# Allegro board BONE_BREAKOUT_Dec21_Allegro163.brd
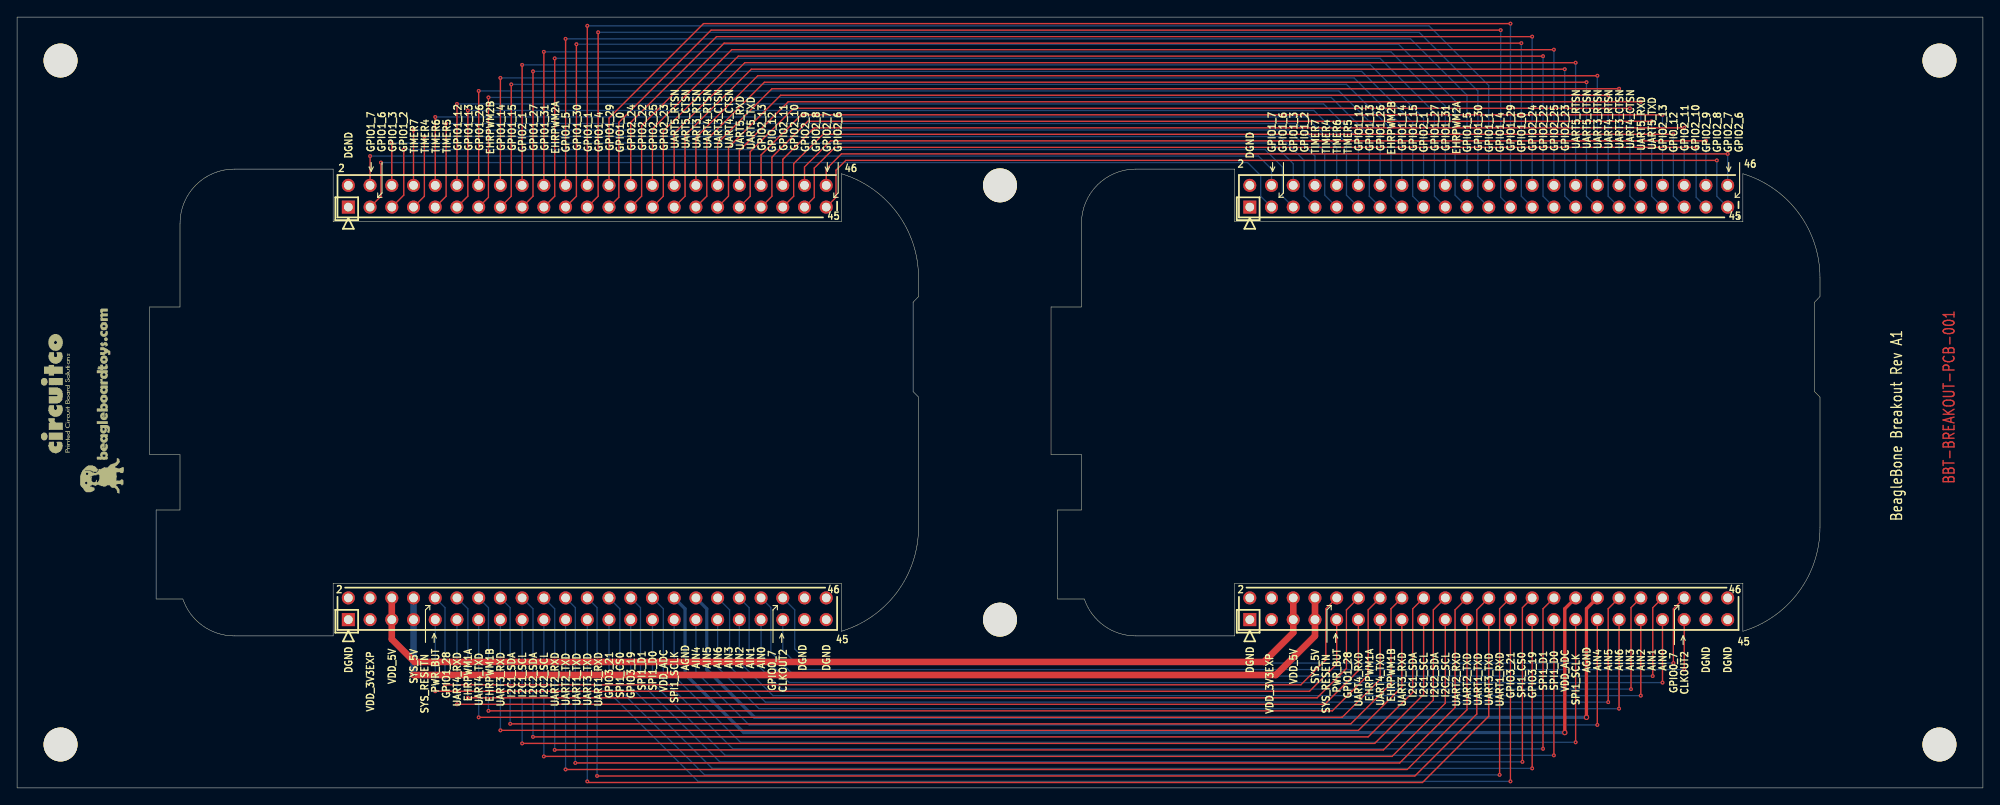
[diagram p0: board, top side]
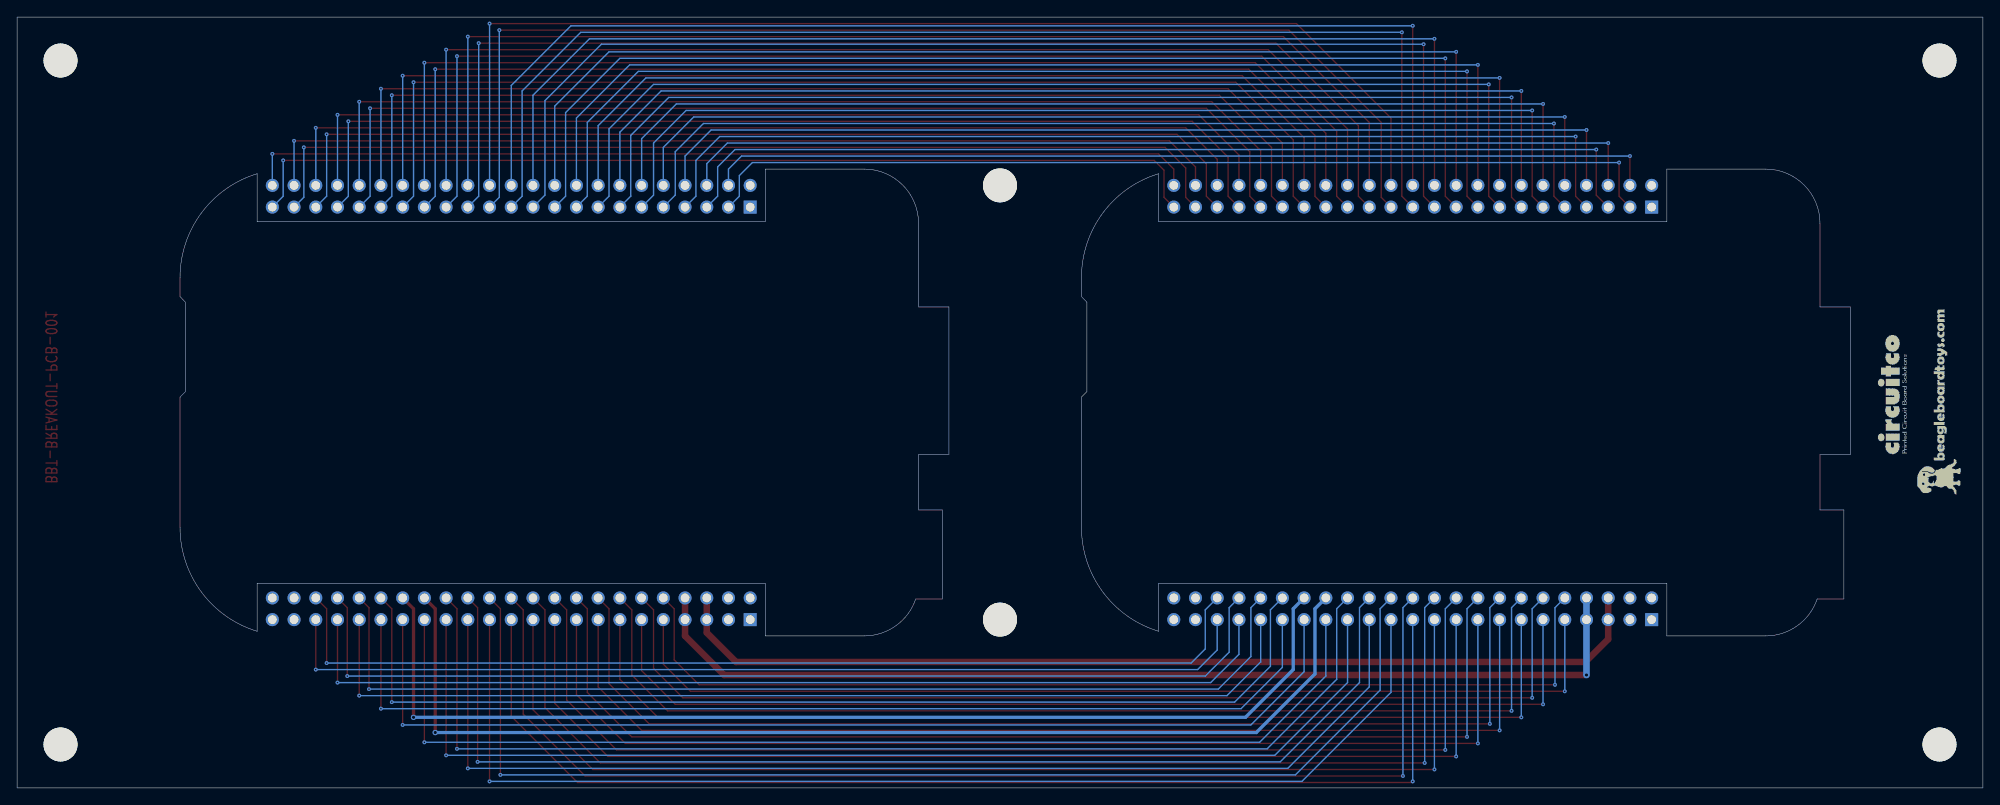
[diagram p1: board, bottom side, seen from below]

Outline 229.87 x 90.17 mm; copper layers: TOP, LYR2-GND, LYR3-PWR, BOTTOM. Coordinates in mm from the lower left corner of the outline.

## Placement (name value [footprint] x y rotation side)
NOREF  -  []  -339.09 -213.36 0 top
NOREF#2  -  [unnamed#2]  19.05 17.78 0 top
P1  FEMALE HEADER 2x23  [2X23_HDR_FEMALE]  38.73 67.94 180 top
P2  FEMALE HEADER 2x23  [2X23_HDR_FEMALE]  38.73 19.69 180 top
P3  FEMALE HEADER 2x23  [2X23_HDR_FEMALE]  144.15 67.94 180 top
P4  FEMALE HEADER 2x23  [2X23_HDR_FEMALE]  144.15 19.69 180 top

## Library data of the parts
P1-P4 = FEMALE HEADER 2x23

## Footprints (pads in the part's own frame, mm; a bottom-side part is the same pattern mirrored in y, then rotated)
2X23_HDR_FEMALE
  rect 1.524x1.524 hole 1.016: 1(0,0)
  round 1.524 hole 1.016: 2(0,-2.54) 3(-2.54,0) 4(-2.54,-2.54) 5(-5.08,0) 6(-5.08,-2.54) 7(-7.62,0) 8(-7.62,-2.54) 9(-10.16,0) 10(-10.16,-2.54) 11(-12.7,0) 12(-12.7,-2.54) 13(-15.24,0) 14(-15.24,-2.54) 15(-17.78,0) 16(-17.78,-2.54) 17(-20.32,0) 18(-20.32,-2.54) 19(-22.86,0) 20(-22.86,-2.54) 21(-25.4,0) 22(-25.4,-2.54) 23(-27.94,0) 24(-27.94,-2.54) 25(-30.48,0) 26(-30.48,-2.54) 27(-33.02,0) 28(-33.02,-2.54) 29(-35.56,0) 30(-35.56,-2.54) 31(-38.1,0) 32(-38.1,-2.54) 33(-40.64,0) 34(-40.64,-2.54) 35(-43.18,0) 36(-43.18,-2.54) 37(-45.72,0) 38(-45.72,-2.54) 39(-48.26,0) 40(-48.26,-2.54) 41(-50.8,0) 42(-50.8,-2.54) 43(-53.34,0) 44(-53.34,-2.54) 45(-55.88,0) 46(-55.88,-2.54)
unnamed#2
  round 3.962 hole 3.962 unplated: (-13.97,67.31) (-13.97,-12.7) (95.885,52.705) (95.885,1.905) (205.74,67.31) (205.74,-12.7)

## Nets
AGND: P2.34 P4.34
DGND: P1.1 P1.2 P2.1 P2.2 P2.43 P2.44 P2.45 P2.46 P3.1 P3.2 P4.1 P4.2 P4.43 P4.44 P4.45 P4.46
VDD_3V3EXP: P2.3 P2.4 P4.3 P4.4
VDD_5V: P2.5 P2.6 P4.5 P4.6
VDD_ADC: P2.32 P4.32
AIN0: P2.39 P4.39
AIN1: P2.40 P4.40
AIN2: P2.37 P4.37
AIN3: P2.38 P4.38
AIN4: P2.33 P4.33
AIN5: P2.36 P4.36
AIN6: P2.35 P4.35
CLKOUT2: P2.41 P4.41
EHRPWM1A: P2.14 P4.14
EHRPWM1B: P2.16 P4.16
EHRPWM2A: P1.19 P3.19
EHRPWM2B: P1.13 P3.13
GPIO0_7: P2.42 P4.42
GPIO1_0: P1.25 P3.25
GPIO1_1: P1.24 P3.24
GPIO1_2: P1.5 P3.5
GPIO1_3: P1.6 P3.6
GPIO1_4: P1.23 P3.23
GPIO1_5: P1.22 P3.22
GPIO1_6: P1.3 P3.3
GPIO1_7: P1.4 P3.4
GPIO1_12: P1.12 P3.12
GPIO1_13: P1.11 P3.11
GPIO1_14: P1.16 P3.16
GPIO1_15: P1.15 P3.15
GPIO1_26: P1.14 P3.14
GPIO1_27: P1.17 P3.17
GPIO1_28: P2.12 P4.12
GPIO1_29: P1.26 P3.26
GPIO1_30: P1.21 P3.21
GPIO1_31: P1.20 P3.20
GPIO2_1: P1.18 P3.18
GPIO2_6: P1.45 P3.45
GPIO2_7: P1.46 P3.46
GPIO2_8: P1.43 P3.43
GPIO2_9: P1.44 P3.44
GPIO2_10: P1.41 P3.41
GPIO2_11: P1.42 P3.42
GPIO2_13: P1.40 P3.40
GPIO2_22: P1.27 P3.27
GPIO2_23: P1.29 P3.29
GPIO2_24: P1.28 P3.28
GPIO2_25: P1.30 P3.30
GPIO3_19: P2.27 P4.27
GPIO3_21: P2.25 P4.25
GPIO_12: P1.39 P3.39
I2C1_SCL: P2.17 P4.17
I2C1_SDA: P2.18 P4.18
I2C2_SCL: P2.19 P4.19
I2C2_SDA: P2.20 P4.20
PWR_BUT: P2.9 P4.9
SPI1_CS0: P2.28 P4.28
SPI1_D0: P2.29 P4.29
SPI1_D1: P2.30 P4.30
SPI1_SCLK: P2.31 P4.31
SYS_5V: P2.7 P2.8 P4.7 P4.8
SYS_RESETN: P2.10 P4.10
TIMER4: P1.7 P3.7
TIMER5: P1.9 P3.9
TIMER6: P1.10 P3.10
TIMER7: P1.8 P3.8
UART1_RXD: P2.26 P4.26
UART1_TXD: P2.24 P4.24
UART2_RXD: P2.22 P4.22
UART2_TXD: P2.21 P4.21
UART3_CTSN: P1.36 P3.36
UART3_RTSN: P1.34 P3.34
UART3_RXD: P2.15 P4.15
UART3_TXD: P2.23 P4.23
UART4_CTSN: P1.35 P3.35
UART4_RTSN: P1.33 P3.33
UART4_RXD: P2.11 P4.11
UART4_TXD: P2.13 P4.13
UART5_CTSN: P1.31 P3.31
UART5_RTSN: P1.32 P3.32
UART5_RXD: P1.38 P3.38
UART5_TXD: P1.37 P3.37

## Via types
v1: diameter 0.457, hole 0.203, TOP to BOTTOM, 76 vias
v2: diameter 0.635, hole 0.381, TOP to BOTTOM, 3 vias

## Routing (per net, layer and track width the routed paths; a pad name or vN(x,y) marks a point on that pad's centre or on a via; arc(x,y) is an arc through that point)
AGND: length 128.6
  TOP w0.381: v2(183.52,8.26) 183.52,20.96 P4.34
  BOTTOM w0.381: P2.34 80.64,20.96 80.64,13.84 86.23,8.26 v2(183.52,8.26)
DGND: length 76.2
  LYR2-GND w0.66: 196.64,18.84 P4.43 ; P4.43 198.33,18.84 ; P4.43 196.64,20.53 ; P4.43 198.33,20.53 ; P2.45 95.46,20.53 ; P2.45 93.77,20.53 ; P2.45 95.46,18.84 ; P2.45 93.77,18.84 ; P4.45 200.87,20.53 ; P4.45 199.18,20.53 ; P4.45 199.18,18.84 ; P4.45 200.87,18.84 ; 143.3,21.38 P4.2 ; P4.2 143.3,23.07 ; P4.2 144.99,23.07 ; P4.2 144.99,21.38 ; P1.1 39.58,68.79 ; P1.1 37.89,68.79 ; P1.1 39.58,67.1 ; P1.1 37.89,67.1 ; P4.1 144.99,20.53 ; P4.1 144.99,18.84 ; P4.1 143.3,18.84 ; P4.1 143.3,20.53 ; P1.2 39.58,69.64 ; P1.2 37.89,71.33 ; P1.2 39.58,71.33 ; P1.2 37.89,69.64 ; P2.1 39.58,18.84 ; P2.1 37.89,18.84 ; P2.1 39.58,20.53 ; P2.1 37.89,20.53 ; 91.23,23.07 P2.44 ; P2.44 92.92,21.38 ; P2.44 92.92,23.07 ; P2.44 91.23,21.38 ; P3.1 144.99,67.1 ; P3.1 143.3,67.1 ; P3.1 143.3,68.79 ; P3.1 144.99,68.79 ; 143.3,69.64 P3.2 ; P3.2 144.99,69.64 ; P3.2 143.3,71.33 ; P3.2 144.99,71.33 ; P4.44 198.33,23.07 ; P4.44 198.33,21.38 ; P4.44 196.64,23.07 ; P4.44 196.64,21.38 ; 37.89,21.38 P2.2 ; P2.2 37.89,23.07 ; P2.2 39.58,21.38 ; P2.2 39.58,23.07 ; 199.18,21.38 P4.46 ; P4.46 200.87,23.07 ; P4.46 200.87,21.38 ; P4.46 199.18,23.07 ; P2.43 92.92,20.53 ; P2.43 91.23,18.84 ; P2.43 92.92,18.84 ; P2.43 91.23,20.53 ; P2.46 95.46,21.38 ; P2.46 93.77,21.38 ; P2.46 93.77,23.07 ; P2.46 95.46,23.07
VDD_3V3EXP: length 19
  LYR3-PWR w0.66: 40.43,20.53 P2.3 ; P2.3 42.12,20.53 ; P2.3 40.43,18.84 ; P2.3 42.12,18.84 ; 40.43,23.07 P2.4 ; P2.4 42.12,21.38 ; P2.4 42.12,23.07 ; P2.4 40.43,21.38 ; P4.4 147.53,23.07 ; P4.4 147.53,21.38 ; P4.4 145.84,21.38 ; P4.4 145.84,23.07 ; 145.84,18.84 P4.3 ; P4.3 147.53,20.53 ; P4.3 147.53,18.84 ; P4.3 145.84,20.53
VDD_5V: length 116.8
  TOP w0.762: P2.6 P2.5 43.81,17.4 46.48,14.73 145.8,14.73 149.23,18.16 P4.5 P4.6
VDD_ADC: length 131.4
  TOP w0.381: P4.32 180.98,20.96 v2(180.98,6.48)
  BOTTOM w0.381: P2.32 78.11,20.96 78.11,13.34 84.96,6.48 v2(180.98,6.48)
AIN0: length 118.2
  TOP w0.152: v1(192.41,12.32) P4.39
  BOTTOM w0.152: v1(192.41,12.32) 90.3,12.32 86.99,15.62 P2.39
AIN1: length 120.7
  TOP w0.152: P4.40 191.26,21.08 v1(191.26,13.08)
  BOTTOM w0.152: v1(191.26,13.08) 90.93,13.08 88.14,15.88 88.14,21.08 P2.40
AIN2: length 120.9
  TOP w0.152: v1(189.87,10.8) P4.37
  BOTTOM w0.152: P2.37 84.45,14.73 88.39,10.8 v1(189.87,10.8)
AIN3: length 123.2
  TOP w0.152: v1(188.72,11.56) 188.72,21.08 P4.38
  BOTTOM w0.152: P2.38 85.6,21.08 85.6,15.37 89.41,11.56 v1(188.72,11.56)
AIN4: length 126.4
  TOP w0.152: v1(184.79,7.37) P4.33
  BOTTOM w0.152: P2.33 79.38,13.59 85.6,7.37 v1(184.79,7.37)
AIN5: length 125.8
  TOP w0.152: P4.36 186.06,20.96 v1(186.06,10.03)
  BOTTOM w0.152: v1(186.06,10.03) 87.5,10.03 83.31,14.22 83.31,20.83 P2.36
AIN6: length 123.4
  TOP w0.152: v1(187.33,9.27) P4.35
  BOTTOM w0.152: P2.35 81.92,14.1 86.74,9.27 v1(187.33,9.27)
CLKOUT2: length 115.8
  TOP w0.152: 194.95,19.69 v1(194.95,13.84)
  BOTTOM w0.152: P2.41 89.53,16.13 91.82,13.84 v1(194.95,13.84)
EHRPWM1A: length 127.9
  TOP w0.152: P4.14 157.99,20.83 157.99,13.21 153.8,9.02 v1(55.12,9.02)
  BOTTOM w0.152: v1(55.12,9.02) 55.12,21.08 P2.14
EHRPWM1B: length 130.7
  TOP w0.152: v1(57.66,7.49) 155.96,7.49 160.66,12.19 160.66,20.96 P4.16
  BOTTOM w0.152: v1(57.66,7.49) 57.66,21.08 P2.16
EHRPWM2A: length 135
  TOP w0.152: v1(62.86,85.34) 62.86,69.22 P1.19
  BOTTOM w0.152: v1(62.86,85.34) 159.39,85.34 165.74,78.99 165.74,69.22 167.01,67.94
EHRPWM2B: length 127
  TOP w0.152: P1.13 55.12,69.09 v1(55.12,80.77)
  BOTTOM w0.152: P3.13 158.12,69.22 158.12,76.33 153.67,80.77 v1(55.12,80.77)
GPIO0_7: length 118.1
  TOP w0.152: 194.95,22.23 193.68,20.96 v1(193.68,14.61)
  BOTTOM w0.152: v1(193.68,14.61) 92.58,14.61 90.93,16.26 90.93,20.83 P2.42
GPIO1_0: length 139.1
  TOP w0.152: P1.25 70.36,69.09 70.36,77.85 81.15,88.65 v1(173.48,88.65)
  BOTTOM w0.152: P3.25 173.48,69.09 v1(173.48,88.65)
GPIO1_1: length 138.7
  TOP w0.152: v1(66.67,89.15) P1.24
  BOTTOM w0.152: v1(66.67,89.15) 165.1,89.15 172.09,82.17 P3.24
GPIO1_2: length 116.1
  TOP w0.152: P1.5 45.21,69.34 v1(45.21,74.68)
  BOTTOM w0.152: v1(45.21,74.68) 145.92,74.68 147.96,72.64 147.96,69.22 P3.5
GPIO1_3: length 113.9
  TOP w0.152: v1(43.81,75.44) P1.6
  BOTTOM w0.152: v1(43.81,75.44) 146.81,75.44 149.23,73.03 P3.6
GPIO1_4: length 140.8
  TOP w0.152: P1.23 67.95,69.22 v1(67.95,88.39)
  BOTTOM w0.152: v1(67.95,88.39) 163.96,88.39 170.81,81.53 170.81,69.22 P3.23
GPIO1_5: length 135.8
  TOP w0.152: P1.22 v1(64.14,87.63)
  BOTTOM w0.152: v1(64.14,87.63) 162.94,87.63 169.55,81.03 P3.22
GPIO1_6: length 113.4
  TOP w0.152: v1(42.55,73.15) 42.55,69.22 P1.3
  BOTTOM w0.152: P3.3 145.41,69.21 145.41,71.63 143.89,73.15 v1(42.55,73.15)
GPIO1_7: length 111.4
  TOP w0.152: v1(41.28,73.91) P1.4
  BOTTOM w0.152: P3.4 146.69,72.39 145.16,73.91 v1(41.28,73.91)
GPIO1_12: length 122.1
  TOP w0.152: v1(51.44,80.01) P1.12
  BOTTOM w0.152: v1(51.44,80.01) 152.78,80.01 156.84,75.95 P3.12
GPIO1_13: length 124.2
  TOP w0.152: P1.11 52.7,69.22 v1(52.7,79.25)
  BOTTOM w0.152: P3.11 155.45,69.34 155.45,75.44 151.64,79.25 v1(52.7,79.25)
GPIO1_14: length 127.3
  TOP w0.152: P1.16 v1(56.52,83.06)
  BOTTOM w0.152: v1(56.52,83.06) 156.34,83.06 161.93,77.47 P3.16
GPIO1_15: length 129.6
  TOP w0.152: v1(57.78,82.3) 57.78,69.22 P1.15
  BOTTOM w0.152: P3.15 160.66,69.22 160.66,77.09 155.45,82.3 v1(57.78,82.3)
GPIO1_26: length 124.7
  TOP w0.152: P1.14 v1(53.97,81.53)
  BOTTOM w0.152: P3.14 159.39,76.71 154.56,81.53 v1(53.97,81.53)
GPIO1_27: length 132.2
  TOP w0.152: P1.17 60.33,69.22 v1(60.33,83.82)
  BOTTOM w0.152: P3.17 163.2,69.22 163.2,77.85 157.23,83.82 v1(60.33,83.82)
GPIO1_28: length 125.2
  TOP w0.152: v1(52.7,10.54) 152.02,10.54 155.45,13.97 155.45,20.83 P4.12
  BOTTOM w0.152: v1(52.7,10.54) 52.7,20.96 P2.12
GPIO1_29: length 136.8
  TOP w0.152: P1.26 69.22,78.36 80.26,89.41 v1(174.62,89.41)
  BOTTOM w0.152: v1(174.62,89.41) P3.26
GPIO1_30: length 138.1
  TOP w0.152: P1.21 65.41,69.22 v1(65.41,87)
  BOTTOM w0.152: v1(65.41,87) 161.54,87 168.15,80.39 168.15,69.34 P3.21
GPIO1_31: length 132.9
  TOP w0.152: P1.20 v1(61.59,86.11)
  BOTTOM w0.152: 167.01,70.48 167.01,79.76 160.66,86.11 v1(61.59,86.11)
GPIO2_1: length 130
  TOP w0.152: P1.18 v1(59.06,84.58)
  BOTTOM w0.152: P3.18 164.47,78.36 158.24,84.58 v1(59.06,84.58)
GPIO2_6: length 114.2
  TOP w0.152: P1.45 95.76,69.09 95.76,72.26 96.9,73.41 v1(198.76,73.41)
  BOTTOM w0.152: v1(198.76,73.41) 198.76,69.22 P3.45
GPIO2_7: length 111.7
  TOP w0.152: P1.46 94.61,72.39 96.39,74.17 v1(200.03,74.17)
  BOTTOM w0.152: v1(200.03,74.17) P3.46
GPIO2_8: length 116.6
  TOP w0.152: v1(196.34,74.93) 95.63,74.93 93.22,72.52 93.22,69.09 P1.43
  BOTTOM w0.152: P3.43 196.34,69.09 v1(196.34,74.93)
GPIO2_9: length 114
  TOP w0.152: P1.44 92.08,72.64 95.12,75.69 v1(197.49,75.69)
  BOTTOM w0.152: P3.44 v1(197.49,75.69)
GPIO2_10: length 118.9
  TOP w0.152: v1(193.68,76.45) 94.23,76.45 90.8,73.03 90.8,69.22 P1.41
  BOTTOM w0.152: 194.95,67.94 193.68,69.22 v1(193.68,76.45)
GPIO2_11: length 116.7
  TOP w0.152: v1(194.95,77.22) 93.22,77.22 89.53,73.53 P1.42
  BOTTOM w0.152: 194.95,70.48 v1(194.95,77.22)
GPIO2_13: length 119.2
  TOP w0.152: P1.40 86.99,74.04 91.69,78.74 v1(192.41,78.74)
  BOTTOM w0.152: P3.40 v1(192.41,78.74)
GPIO2_22: length 136.6
  TOP w0.152: v1(175.9,87.12) 82.68,87.12 73.03,77.47 73.03,69.22 P1.27
  BOTTOM w0.152: v1(175.9,87.12) 175.9,69.22 P3.27
GPIO2_23: length 134.1
  TOP w0.152: v1(178.44,85.6) 84.33,85.6 75.56,76.84 75.56,69.22 74.3,67.94
  BOTTOM w0.152: P3.29 178.44,69.22 v1(178.44,85.6)
GPIO2_24: length 134.3
  TOP w0.152: P1.28 71.75,77.85 81.79,87.88 v1(177.17,87.88)
  BOTTOM w0.152: v1(177.17,87.88) P3.28
GPIO2_25: length 131.7
  TOP w0.152: 74.3,70.48 74.3,77.09 83.57,86.36 v1(179.71,86.36)
  BOTTOM w0.152: v1(179.71,86.36) P3.30
GPIO3_19: length 134.6
  TOP w0.152: v1(177.17,2.29) P4.27
  BOTTOM w0.152: v1(177.17,2.29) 81.28,2.29 71.75,11.81 P2.27
GPIO3_21: length 137.2
  TOP w0.152: P4.25 v1(174.62,0.76)
  BOTTOM w0.152: v1(174.62,0.76) 79.63,0.76 69.22,11.18 P2.25
GPIO_12: length 121.5
  TOP w0.152: v1(191.14,77.98) 92.46,77.98 88.27,73.79 88.27,69.22 P1.39
  BOTTOM w0.152: P3.39 191.14,69.22 v1(191.14,77.98)
I2C1_SCL: length 131
  TOP w0.152: v1(59.06,5.21) 158.75,5.21 164.47,10.92 P4.17
  BOTTOM w0.152: P2.17 v1(59.06,5.21)
I2C1_SDA: length 133.4
  TOP w0.152: P4.18 163.2,20.96 163.2,11.18 157.99,5.97 v1(60.33,5.97)
  BOTTOM w0.152: P2.18 60.33,20.96 v1(60.33,5.97)
I2C2_SCL: length 133.8
  TOP w0.152: v1(61.59,3.68) 160.78,3.68 167.01,9.91 167.01,19.69
  BOTTOM w0.152: P2.19 v1(61.59,3.68)
I2C2_SDA: length 136
  TOP w0.152: 167.01,22.23 165.61,20.83 165.61,10.29 159.77,4.45 v1(62.86,4.45)
  BOTTOM w0.152: v1(62.86,4.45) 62.86,20.96 P2.20
PWR_BUT: length 120.3
  TOP w0.152: P4.9 154.31,14.48 151.13,11.3 v1(48.89,11.3)
  BOTTOM w0.152: P2.9 v1(48.89,11.3)
SPI1_CS0: length 137
  TOP w0.152: P4.28 176.02,21.08 v1(176.02,3.05)
  BOTTOM w0.152: v1(176.02,3.05) 82.17,3.05 72.9,12.32 72.9,21.08 P2.28
SPI1_D0: length 132.2
  TOP w0.152: v1(179.71,3.81) P4.29
  BOTTOM w0.152: v1(179.71,3.81) 82.8,3.81 74.3,12.32 74.3,19.69
SPI1_D1: length 134.5
  TOP w0.152: v1(178.44,4.57) 178.44,20.96 P4.30
  BOTTOM w0.152: v1(178.44,4.57) 83.69,4.57 75.56,12.7 75.56,20.96 74.3,22.23
SPI1_SCLK: length 129.6
  TOP w0.152: v1(182.25,5.33) P4.31
  BOTTOM w0.152: v1(182.25,5.33) 84.58,5.33 76.83,13.08 P2.31
SYS_5V: length 120.8
  TOP w0.762: v2(46.36,13.21) 147.19,13.21 151.77,17.78 P4.7 P4.8
  BOTTOM w0.762: P2.8 P2.7 v2(46.36,13.21)
SYS_RESETN: length 122.6
  TOP w0.152: P4.10 153.04,20.96 153.04,14.99 150.11,12.07 v1(50.04,12.07)
  BOTTOM w0.152: v1(50.04,12.07) 50.04,21.08 P2.10
TIMER4: length 118.8
  TOP w0.152: P1.7 47.62,69.22 v1(47.62,76.2)
  BOTTOM w0.152: v1(47.62,76.2) 147.7,76.2 150.5,73.41 150.5,69.22 P3.7
TIMER5: length 121.5
  TOP w0.152: P1.9 50.16,69.22 v1(50.16,77.72)
  BOTTOM w0.152: v1(50.16,77.72) 149.61,77.72 152.91,74.42 152.91,69.34 P3.9
TIMER6: length 119.3
  TOP w0.152: P1.10 v1(48.89,78.49)
  BOTTOM w0.152: v1(48.89,78.49) 150.75,78.49 154.31,74.93 P3.10
TIMER7: length 116.6
  TOP w0.152: v1(46.36,76.96) P1.8
  BOTTOM w0.152: v1(46.36,76.96) 148.72,76.96 151.77,73.91 P3.8
UART1_RXD: length 139.5
  TOP w0.152: v1(173.36,1.52) 173.36,20.96 P4.26
  BOTTOM w0.152: P2.26 70.48,20.96 70.48,11.43 80.39,1.52 v1(173.36,1.52)
UART1_TXD: length 141.3
  TOP w0.152: v1(67.82,1.4) 163.45,1.4 170.69,8.64 170.69,20.83 P4.24
  BOTTOM w0.152: v1(67.82,1.4) 67.82,21.08 P2.24
UART2_RXD: length 138.7
  TOP w0.152: P4.22 168.15,20.83 168.15,9.4 161.67,2.92 v1(65.28,2.92)
  BOTTOM w0.152: P2.22 65.28,21.08 v1(65.28,2.92)
UART2_TXD: length 136.4
  TOP w0.152: v1(64.14,2.16) 162.56,2.16 169.55,9.14 P4.21
  BOTTOM w0.152: P2.21 v1(64.14,2.16)
UART3_CTSN: length 124.3
  TOP w0.152: v1(187.33,81.79) 88.27,81.79 81.92,75.44 P1.36
  BOTTOM w0.152: v1(187.33,81.79) P3.36
UART3_RTSN: length 126.8
  TOP w0.152: v1(184.79,83.31) 86.61,83.31 79.38,76.07 P1.34
  BOTTOM w0.152: v1(184.79,83.31) P3.34
UART3_RXD: length 128.3
  TOP w0.152: v1(56.52,6.73) 156.84,6.73 161.93,11.81 P4.15
  BOTTOM w0.152: P2.15 v1(56.52,6.73)
UART3_TXD: length 138.9
  TOP w0.152: P4.23 172.09,8.38 164.34,0.64 66.8,0.64 v1(66.67,0.76)
  BOTTOM w0.152: P2.23 v1(66.67,0.76)
UART4_CTSN: length 126.5
  TOP w0.152: P1.35 83.19,69.22 83.19,74.93 89.28,81.03 v1(186.06,81.03)
  BOTTOM w0.152: v1(186.06,81.03) 186.06,69.22 P3.35
UART4_RTSN: length 129.2
  TOP w0.152: P1.33 80.64,69.22 80.64,75.82 87.38,82.55 v1(183.52,82.55)
  BOTTOM w0.152: P3.33 183.52,69.22 v1(183.52,82.55)
UART4_RXD: length 122.9
  TOP w0.152: v1(51.44,9.78) 152.91,9.78 156.84,13.72 P4.11
  BOTTOM w0.152: P2.11 v1(51.44,9.78)
UART4_TXD: length 125.7
  TOP w0.152: P4.13 159.39,12.7 154.94,8.26 v1(53.97,8.26)
  BOTTOM w0.152: P2.13 v1(53.97,8.26)
UART5_CTSN: length 131.6
  TOP w0.152: v1(180.98,84.07) 85.85,84.07 78.11,76.33 78.11,69.22 P1.31
  BOTTOM w0.152: P3.31 180.98,69.22 v1(180.98,84.07)
UART5_RTSN: length 129.3
  TOP w0.152: P1.32 76.83,76.58 85.09,84.84 v1(182.25,84.84)
  BOTTOM w0.152: v1(182.25,84.84) P3.32
UART5_RXD: length 121.6
  TOP w0.152: v1(189.87,80.26) 90.17,80.26 84.45,74.55 P1.38
  BOTTOM w0.152: v1(189.87,80.26) P3.38
UART5_TXD: length 124.1
  TOP w0.152: P1.37 85.72,69.22 85.72,74.42 90.8,79.5 v1(188.59,79.5)
  BOTTOM w0.152: v1(188.59,79.5) 188.59,69.22 P3.37

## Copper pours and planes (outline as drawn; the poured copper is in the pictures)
DGND on LYR2-GND: 0.51,0.51 0.51,89.66 229.36,89.66 229.36,0.51 ; 2 cut-outs
VDD_3V3EXP on LYR3-PWR: 0.51,0.51 0.51,89.66 229.36,89.66 229.36,0.51 ; 2 cut-outs

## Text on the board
User.Comments: DATE: | CIRCUITCO ELECTRONICS | 12/08/2011 | BONE BREAKOUT | CUTOUT
TOP: BBT-BREAKOUT-PCB-001
Ref Des/Silkscreen Top: DGND | VDD_3V3EXP | GPIO1_7 | GPIO1_6 | VDD_5V | GPIO1_3 | GPIO1_2 | SYS_5V | TIMER7 | SYS_RESETN | TIMER4 | PWR_BUT | TIMER6 | GPIO1_28 | TIMER5 | UART4_RXD | GPIO1_12 | EHRPWM1A | GPIO1_13 | UART4_TXD | GPIO1_26 | EHRPWM1B | EHRPWM2B | UART3_RXD | GPIO1_14 | I2C1_SDA | GPIO1_15 | GPIO2_1 | I2C1_SCL | I2C2_SDA | GPIO1_27 | I2C2_SCL | GPIO1_31 | UART2_RXD | EHRPWM2A | GPIO1_5 | UART2_TXD | UART1_TXD | GPIO1_30 | UART3_TXD | GPIO1_1 | UART1_RXD | GPIO1_4 | GPIO3_21 | GPIO1_29 | GPIO1_0 | SPI1_CS0 | GPIO3_19 | GPIO2_24 | SPI1_D1 | GPIO2_22 | SPI1_D0 | GPIO2_25 | VDD_ADC | GPIO2_23 | SPI1_SCLK | UART5_RTSN | AGND | UART5_CTSN | AIN4 | UART3_RTSN | AIN5 | UART4_RTSN | AIN6 | UART3_CTSN | AIN3 | UART4_CTSN | AIN2 | UART5_RXD | AIN1 | UART5_TXD | AIN0 | GPIO2_13 | GPIO_12 | GPIO0_7 | CLKOUT2 | GPIO2_11 | GPIO2_10 | GPIO2_9 | GPIO2_8 | GPIO2_7 | GPIO2_6 | BeagleBone Breakout Rev A1
PAGE_OUTLINE: FAB | 7.  SILKSCREEN IS COLOR BLACK | LAYER SCHEDULE | SCALE: NONE | SMASK_BOT | SILK_BOT | SMASK_TOP | SILK_TOP | LAYER 1 | LAYER 2 | LAYER 3 | LAYER 4 | BONE BREAKOUT | CIRCUITCO ELECTRONICS
DIMENSION: ASSY_TOP
ASSY_BOT: ASSY_BOT
LAYER1_TOP: LAYER1_TOP
User.5: LAYER4_BOT
User.6: PMASK_TOP
User.7: PMASK_BOT
User.8: SMASK_TOP
User.9: SMASK_BOT
User.10: SILK_TOP
User.11: SILK_BOT
User.13: LAYER2_GND
User.14: LAYER3_PWR
User.17: FIGURE | SIZE | 8.0 | 15.0 | 40.0 | 156.0 | DRILL CHART: TOP to BOTTOM | ALL UNITS ARE IN MILS | TOLERANCE | +0.0/-8.0 | +3.0/-3.0 | +0.0/-0.0 | PLATED | NON-PLATED | QTY | 76 | 3 | 184 | 6
